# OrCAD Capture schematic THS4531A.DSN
size A
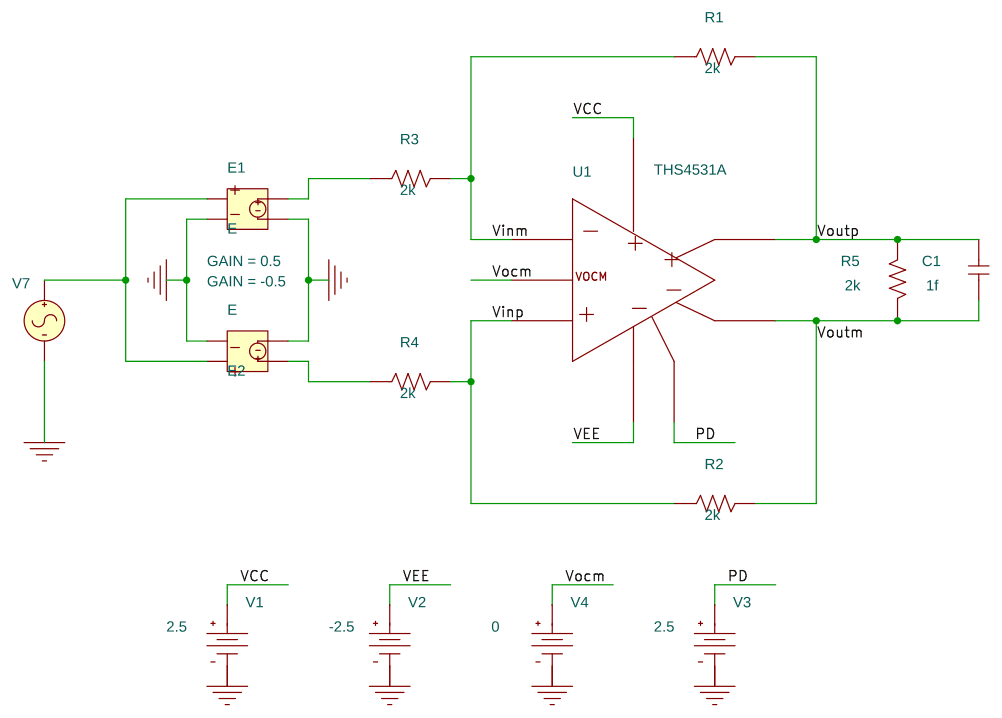
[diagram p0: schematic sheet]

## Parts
C1  1f  [RAD/CK05]
E1  E
E2  E
R1  2k  [AX/RC05]
R2  2k  [AX/RC05]
R3  2k  [AX/RC05]
R4  2k  [AX/RC05]
R5  2k  [AX/RC05]
U1  THS4531A
V1  VDC
V2  VDC
V3  VDC
V4  VDC
V7  VAC

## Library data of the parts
C1 = C
E1 = E: GAIN: 0.5
E2 = E: GAIN: -0.5
R1-R5 = R
U1 = THS4531A
V1 V3 = VDC: DC: 2.5
V2 = VDC: DC: -2.5
V4 = VDC: DC: 0
V7 = VAC

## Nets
VCC: U1.7(VCC) V1.0(+)
VEE: U1.6(VEE) V2.0(+)
Vinm: R1.1 R3.2 U1.4(VINM)
Vinp: R2.1 R4.2 U1.5(VINP)
0: E1.2 E1.4 E2.2 E2.4 V1.1(-) V2.1(-) V3.1(-) V4.1(-) V7.2(-)
PD: U1.8(PD) V3.0(+)
Vocm: U1.3(VOCM) V4.0(+)
Voutm: C1.1 R2.2 R5.1 U1.1(VOUTM)
Voutp: C1.2 R1.2 R5.2 U1.2(VOUTP)
N04978: E1.3 R3.1
N05033: E2.3 R4.1
N06471: E1.1 E2.1 V7.1(+)
